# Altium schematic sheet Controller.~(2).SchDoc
size A; SheetNumber: 2; SheetTotal: 2
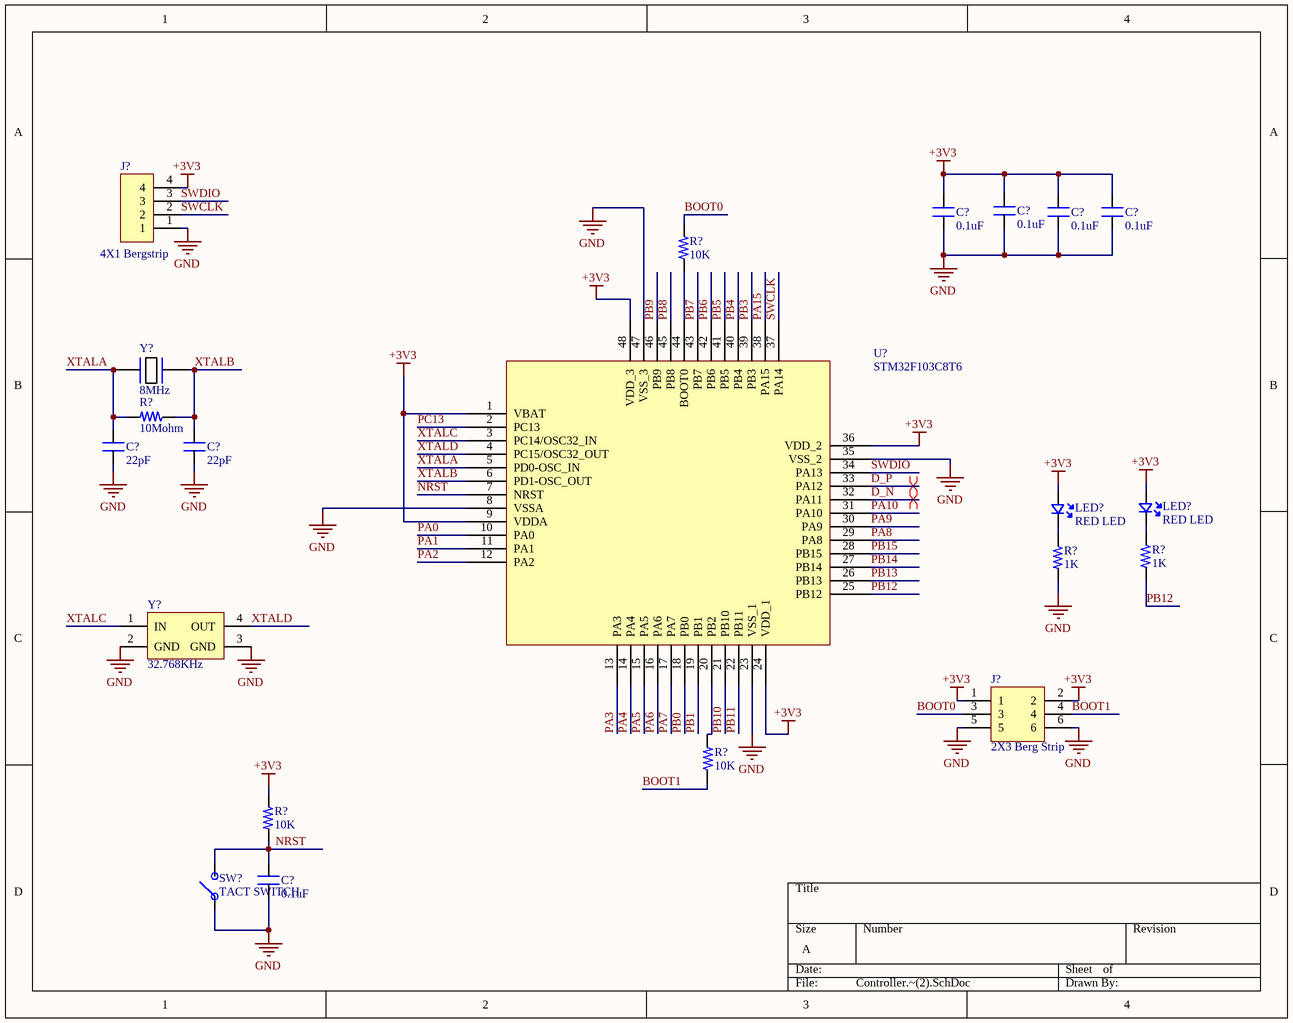
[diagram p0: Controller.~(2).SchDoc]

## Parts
(Parts that share a designator on the sheet are numbered #1, #2 ... from top to bottom, then left to right.)
C?#1  0.1uF  [CAP_0805]
C?#2  0.1uF  [CAP_0805]
C?#3  0.1uF  [CAP_0805]
C?#4  0.1uF  [CAP_0805]
C?#5  22pF  [CAP_0805]
C?#6  22pF  [CAP_0805]
C?#7  0.1uF  [CAP_0805]
J?#1  4X1 Bergstrip  [CON4_100_40D72_TH_ST_MALE]
J?#2  2X3 Berg Strip  [CON6_100_59D78_TH_ST_Duplicate]
LED?#1  RED LED  [LED_0805]
LED?#2  RED LED  [LED_0805]
R?#1  10K  [RES_0805]
R?#2  10Mohm  [RES_0805]
R?#3  1K  [RES_0805]
R?#4  1K  [RES_0805]
R?#5  10K  [RES_0805]
R?#6  10K  [RES_0805]
SW?  TACT SWITCH  [SW_342_SMD]
U?  STM32F103C8T6  [LQFP-48_19.6_393_58X11_SMD]
Y?#1  8MHz  [XTAL_314_240X47_SMD]
Y?#2  32.768KHz  [XTAL_MC-405 32.7680K-G3]

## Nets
+3V3: C?#1.2 C?#2.2 C?#3.2 C?#4.2 J?#1.4 J?#2.1 J?#2.2 LED?#1.A LED?#2.A R?#6.2 U?.1(VBAT) U?.9(VDDA) U?.24(VDD_1) U?.36(VDD_2) U?.48(VDD_3)
GND: C?#1.1 C?#2.1 C?#3.1 C?#4.1 C?#5.1 C?#6.1 C?#7.1 J?#1.1 J?#2.5 J?#2.6 R?#3.1 SW?.1 U?.8(VSSA) U?.23(VSS_1) U?.35(VSS_2) U?.47(VSS_3) Y?#2.2(GND) Y?#2.3(GND)
BOOT0: J?#2.3 R?#1.2
BOOT1: J?#2.4 R?#5.2
D_N: U?.32(PA11)
D_P: U?.33(PA12)
NRST: C?#7.2 R?#6.1 SW?.2 U?.7(NRST)
PA0: U?.10(PA0)
PA1: U?.11(PA1)
PA2: U?.12(PA2)
PA3: U?.13(PA3)
PA4: U?.14(PA4)
PA5: U?.15(PA5)
PA6: U?.16(PA6)
PA7: U?.17(PA7)
PA8: U?.29(PA8)
PA9: U?.30(PA9)
PA10: U?.31(PA10)
PA15: U?.38(PA15)
PB0: U?.18(PB0)
PB1: U?.19(PB1)
PB3: U?.39(PB3)
PB4: U?.40(PB4)
PB5: U?.41(PB5)
PB6: U?.42(PB6)
PB7: U?.43(PB7)
PB8: U?.45(PB8)
PB9: U?.46(PB9)
PB10: U?.21(PB10)
PB11: U?.22(PB11)
PB12: R?#4.1 U?.25(PB12)
PB13: U?.26(PB13)
PB14: U?.27(PB14)
PB15: U?.28(PB15)
PC13: U?.2(PC13)
SWCLK: J?#1.2 U?.37(PA14)
SWDIO: J?#1.3 U?.34(PA13)
XTALA: C?#5.2 R?#2.1 U?.5(PD0-OSC_IN) Y?#1.1
XTALB: C?#6.2 R?#2.2 U?.6(PD1-OSC_OUT) Y?#1.2
XTALC: U?.3(PC14/OSC32_IN) Y?#2.1(IN)
XTALD: U?.4(PC15/OSC32_OUT) Y?#2.4(OUT)
NetLED?#1_K: LED?#1.K R?#3.2
NetLED?#2_K: LED?#2.K R?#4.2
NetR?#1_1: R?#1.1 U?.44(BOOT0)
NetR?#5_1: R?#5.1 U?.20(PB2)

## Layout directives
differential pair; differential pair class diff_90: D_N, D_P

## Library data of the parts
C?#1-C?#4 C?#7 = CAP_0.1uF-50V-5%-0805: 0.1µF ±5% 50V Ceramic Capacitor X7R 0805 (2012 Metric); Manufacturer: KEMET; Manufacturing Part Number: C0805C104J5RACTU
C?#5 C?#6 = CAP_22pF-50V-5%-0805: 22pF ±5% 50V Ceramic Capacitor C0G, NP0 0805 (2012 Metric); Manufacturer: KEMET; Manufacturer Part Number: C0805C220J5GACTU
J?#1 = CON-BS-PLG_4X1-100-TH-ST: 4 pin, 1 row, 2.54mm pitch bergstrip; Manufacturer: NA
J?#2 = CON-BS-PLG_2X3-100-TH-ST: 6 pin, 2 row, 2.54mm pitch bergstrip; Manufacturer: NA
LED?#1 LED?#2 = LED-RED_10mA-0805: Red 621nm LED Indication - Discrete 2V 0805 (2012 Metric); Manufacturer: Lite-On Inc.; Manufacturer Part Number: LTST-C170EKT
R?#1 R?#5 R?#6 = RES_10K-0.125W-1%-0805: 10 kOhms ±1% 0.125W, 1/8W Chip Resistor 0805 (2012 Metric) Moisture Resistant Thick Film; Manufacturer: Yageo; Manufacturing Part Number: RC0805FR-0710KL
R?#2 = RES_10MOHM-0.125W-1%-0805: 10 MOhms ±1% 0.125W, 1/8W Chip Resistor 0805 (2012 Metric) Automotive AEC-Q200, High Voltage Thick Film; Manufacturer: Rohm Semiconductor; Manufacturing Part Number: KTR10EZPF1005
R?#3 R?#4 = RES_1K-0.125W-1%-0805: 1 kOhms ±1% 0.125W, 1/8W Chip Resistor 0805 (2012 Metric) Moisture Resistant Thick Film; Manufacturer: 垈㎵á; Manufacturer Part Number: RC0805FR-071KL
SW? = SW_KSR223GLFG-SMD: Tactile Switch SPST-NO Top Actuated Surface Mount; Manufacturer: C&K
U? = IC-STM32F103C8T6 _1: ARM® Cortex®-M3 STM32F1 Microcontroller IC 32-Bit 72MHz 64KB (64K x 8) FLASH; Manufacturer: STMicroelectronics
Y?#1 = XTAL_8MHZ-LFXTAL030234: Crystals 8MHz 22pF -20C 70C; Manufacturer: IQD Frequency Products; Manufacturing Part Number: LFXTAL030234Reel
Y?#2 = XTAL_32.768KHz-MC-405 32.7680K-G3: Crystals SMD AT XTL MHZ +/-50PPM 12.5 PF 250 T/R; Manufacturer: Epson; Manufacturing Part Number: MC-405 32.7680K-G3: ROHS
